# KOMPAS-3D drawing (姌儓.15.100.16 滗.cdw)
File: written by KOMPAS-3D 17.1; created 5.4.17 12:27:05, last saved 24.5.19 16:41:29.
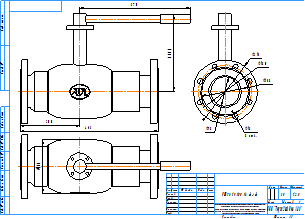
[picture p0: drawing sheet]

Sheet 1: A3, landscape

Title block, sheet 1: name: КШГИ.15.100.16 ф/ф; mass: 35; sheets: 1; organisation: ООО "Торговый дом АДЛ"; sheet format: A3; stored path: C:\Users\kka\KOMPAS_Work\КШП.ГИ\Ду100\КШГИ.15.100.16 ФФ ГЧ _ Кран шаровой газовый изолирующий БИВАЛ Ду100 Ру16 полнопроходной фланцевый Габаритный чертеж.cdw

Views: Вид 1, Проекционный вид 2, Проекционный вид 3
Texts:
  Klimkovich
  ADL
  Рама для чертежей
  Лит-Масса-Масштаб
  Материал-Предприятие
  Масштаб
  Изм.
  Лист
  № докум.
  Подп.
  Дата
  Лит.
  Разраб.
  Пров.
  Т.контр.
  Листов
  Внимание! Данный продукт является объектом авторского права ООО «Торговый Дом АДЛ».
  Запрещается изменение, копирование, распространение
  (в том числе путем копирования на другие сайты и ресурсы в Интернете)
  или любое иное использование информации и объектов без предварительного
  согласия правообладателя (ООО «Торговый Дом АДЛ»).
  Н.контр.
  Утв.
  Изменение
  Номер документа
  Подпись
  Обозначение документа
  Наименование изделия
  Масса изделия по ГОСТ 2.109-73
  Порядковый номер листа
  Общее количество листов в документе
  Характер работы, выполненной лицом, подписавшим документ
  Наименование или индекс предприятия, выпускающего документ
  Инв. № подл.
  Подп. и дата
  Взам. инв. №
  Инв. № дубл.
  Инвентарный номер подлинника по ГОСТ 2.501-68
  Подпись принявшего подлинник в отдел технической документации
  Инвентарный номер подлинника, взамен которого выпущен данный подлинник
  Инвентарный номер дубликата по ГОСТ 2.502-68
  Подпись принявшего дубликат в отдел технической документации
  Справ. №
  Перв. примен.
  Обозначение документа, взамен или на основании которого выпущен данный документ
  Обозначение документа, в котором впервые записан данный документ
  Подпись лица, копировавшего чертеж
  Обозначение формата листа
  !Рама для чертежа
Dimensions and other numbers on the sheet: 463; 370; 258,4; 200; 215; 180; 158; 98; 18; 8 отв.; 1:2,5; 1; 35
